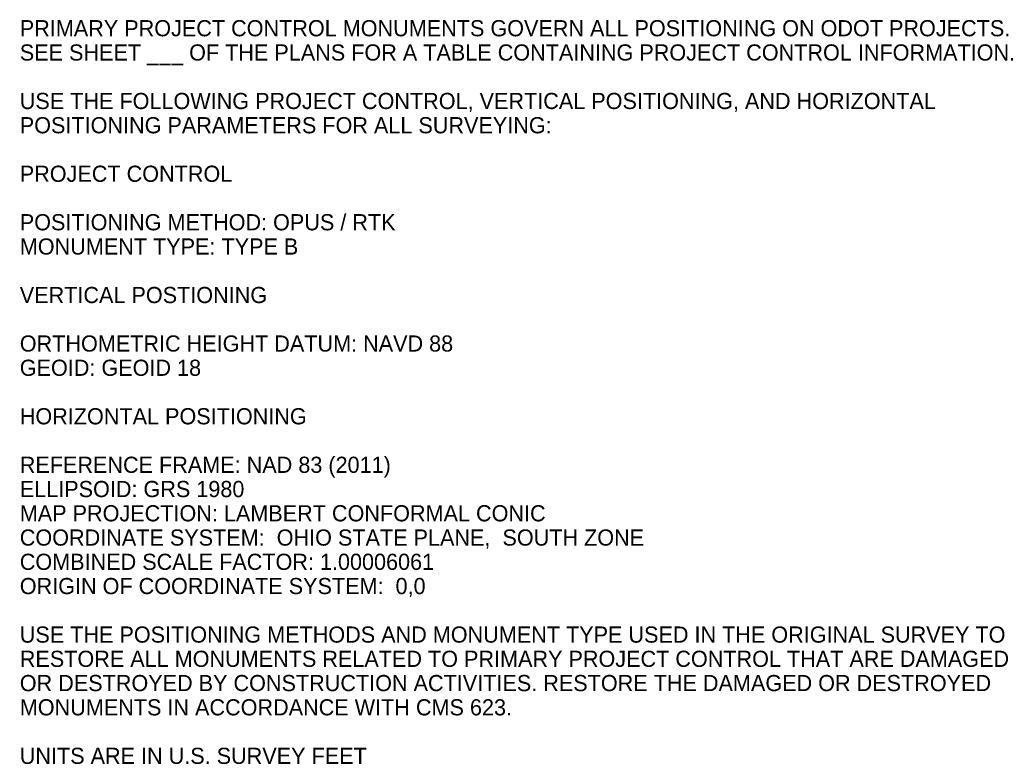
# Model space of a CAD drawing. Extents: x -286 to 93, y -30 to 99.
# Drawn here: x -285.8 to -113.7, y -29.6 to 99.3 of the extents above; entities that cross this region are included whole.
import ezdxf

# ---------------------------------------------------------------- set-up
doc = ezdxf.new("R2010")
doc.units = 0
doc.layers.add('SV_X_Text', color=7, linetype='Continuous')

msp = doc.modelspace()

# ---------------------------------------------------------------- texts
at = {"layer": 'SV_X_Text'}
for s, p in [('PRIMARY PROJECT CONTROL MONUMENTS GOVERN ALL POSITIONING ON ODOT PROJECTS.', (-285.79, 96.46)), ('SEE SHEET ___ OF THE PLANS FOR A TABLE CONTAINING PROJECT CONTROL INFORMATION.', (-285.79, 92.26)), ('USE THE FOLLOWING PROJECT CONTROL, VERTICAL POSITIONING, AND HORIZONTAL', (-285.79, 83.86)), ('POSITIONING PARAMETERS FOR ALL SURVEYING:', (-285.79, 79.66)), ('PROJECT CONTROL', (-285.79, 71.26)), ('POSITIONING METHOD: OPUS / RTK', (-285.79, 62.86)), ('MONUMENT TYPE: TYPE B', (-285.79, 58.66)), ('VERTICAL POSTIONING', (-285.79, 50.26)), ('ORTHOMETRIC HEIGHT DATUM: NAVD 88', (-285.79, 41.86)), ('GEOID: GEOID 18', (-285.79, 37.66)), ('HORIZONTAL POSITIONING', (-285.79, 29.26)), ('REFERENCE FRAME: NAD 83 (2011)', (-285.79, 20.86)), ('ELLIPSOID: GRS 1980', (-285.79, 16.66)), ('MAP PROJECTION: LAMBERT CONFORMAL CONIC', (-285.79, 12.46)), ('COORDINATE SYSTEM:  OHIO STATE PLANE,  SOUTH ZONE', (-285.79, 8.26)), ('COMBINED SCALE FACTOR: 1.00006061', (-285.79, 4.06)), ('ORIGIN OF COORDINATE SYSTEM:  0,0', (-285.79, -0.14)), ('USE THE POSITIONING METHODS AND MONUMENT TYPE USED IN THE ORIGINAL SURVEY TO', (-285.79, -8.54)), ('RESTORE ALL MONUMENTS RELATED TO PRIMARY PROJECT CONTROL THAT ARE DAMAGED', (-285.79, -12.74)), ('OR DESTROYED BY CONSTRUCTION ACTIVITIES. RESTORE THE DAMAGED OR DESTROYED', (-285.79, -16.94)), ('MONUMENTS IN ACCORDANCE WITH CMS 623.', (-285.79, -21.14)), ('UNITS ARE IN U.S. SURVEY FEET', (-285.79, -29.54))]:
    msp.add_text(s, height=2.8, dxfattribs=at).set_placement(p)

doc.saveas('drawing.dxf')
